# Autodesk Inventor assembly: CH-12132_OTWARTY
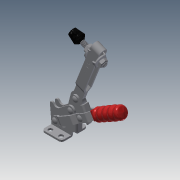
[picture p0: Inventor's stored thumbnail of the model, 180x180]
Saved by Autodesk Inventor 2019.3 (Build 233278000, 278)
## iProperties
Company: Î¢ÈíÖÐ¹ú
Created: 2012-09
Part Number: CH-12132_OTWARTY
Material: Ogólny
Description: STEP AP203
Document SubType Name: Assembly
Designer: CADENGINEERING4
Sending System: SolidWorks 2010
Preprocessor: SwSTEP 2.0
Title: CH-12132.STEP
Author: Î¢ÈíÓÃ»§
Revision Number: ÈÎºÎ
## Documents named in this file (12)
- D:\Vault_2016\Projekty\STRONA\Vertical toggle clamp\Do zrobienia 3\CH-12132\CH-12132_OTWARTY.iam
- D:\Vault_2016\Projekty\STRONA\Vertical toggle clamp\Do zrobienia 3\CH-12132\CH-12130-08.ipt
- D:\Vault_2016\Projekty\STRONA\Vertical toggle clamp\Do zrobienia 3\CH-12132\CH-12130-07.ipt
- D:\Vault_2016\Projekty\STRONA\Vertical toggle clamp\Do zrobienia 3\CH-12132\CH-12130-06.ipt
- D:\Vault_2016\Projekty\STRONA\Vertical toggle clamp\Do zrobienia 3\CH-12132\CH-FW-516.ipt
- D:\Vault_2016\Projekty\STRONA\Vertical toggle clamp\Do zrobienia 3\CH-12132\CH-12130-04 CONNECTING-PLATE.ipt
- D:\Vault_2016\Projekty\STRONA\Vertical toggle clamp\Do zrobienia 3\CH-12132\CH-12130-01 FLANGED BASE.ipt
- D:\Vault_2016\Projekty\STRONA\Vertical toggle clamp\Do zrobienia 3\CH-12132\CH-12130-05.ipt
- D:\Vault_2016\Projekty\STRONA\Vertical toggle clamp\Do zrobienia 3\CH-12132\CH-FC-56212 SPINDLE SUPPLIED.ipt
- D:\Vault_2016\Projekty\STRONA\Vertical toggle clamp\Do zrobienia 3\CH-12132\CH-12130-03 STRAIGHT HANDLE.ipt
- D:\Vault_2016\Projekty\STRONA\Vertical toggle clamp\Do zrobienia 3\CH-12132\CH-FC-56212 Nut.ipt
- D:\Vault_2016\Projekty\STRONA\Vertical toggle clamp\Do zrobienia 3\CH-12132\CH-12132-02 LONG U-BAR.ipt
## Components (15 placed, 11 different names)
1. CH-12130-01 FLANGED BASE_7
2. CH-12130-08:3 — Zestawiające:1, Zestawiające:2, Zestawiające:3, Zestawiające:32
3. CH-12130-07:2 — Zestawiające:16, Zestawiające:17, Zestawiające:18
4. CH-12130-06:3 — Zestawiające:4, Zestawiające:5, Zestawiające:6, Zestawiające:7
5. CH-FW-516:3 — Zestawiające:24, Zestawiające:25, Zestawiające:28
6. CH-12130-08:4 — Zestawiające:10, Zestawiające:11, Zestawiające:12, Zestawiające:13, Zestawiające:14, Zestawiające:15
7. CH-12130-04 CONNECTING-PLATE:2 — Zestawiające:4, Zestawiające:6, Zestawiające:7, Zestawiające:8, Zestawiające:9, Zestawiające:10, Zestawiające:11, Zestawiające:20
8. CH-12130-06:4 — Zestawiające:19, Zestawiające:20
9. CH-12130-05:2 — Zestawiające:1, Równoległe:1
10. CH-FW-516:4 — Zestawiające:23, Zestawiające:26, Zestawiające:27
11. CH-FC-56212 SPINDLE SUPPLIED:2 — Zestawiające:21, Równoległe:2
12. CH-12130-03 STRAIGHT HANDLE:2 — Zestawiające:2, Zestawiające:3, Zestawiające:9, Zestawiające:12, Zestawiające:13, Zestawiające:14, Zestawiające:15, Zestawiające:16, Zestawiające:17, Zestawiające:18, Zestawiające:32
13. CH-FC-56212 Nut:3 — Zestawiające:21, Zestawiające:22, Zestawiające:28
14. CH-FC-56212 Nut:4 — Zestawiające:22, Zestawiające:23, Zestawiające:24, Zestawiające:27, Zestawiające:29, Zestawiające:30
15. CH-12132-02 LONG U-BAR:2 — Równoległe:1, Zestawiające:5, Zestawiające:8, Zestawiające:19, Zestawiające:25, Zestawiające:26, Równoległe:2, Zestawiające:29, Zestawiające:30
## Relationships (33: Mate 31, Flush 2)
- Zestawiające:1 [Mate]: CH-12130-08:3 ↔ CH-12130-05:2
- Zestawiające:2 [Mate]: CH-12130-08:3 ↔ CH-12130-03 STRAIGHT HANDLE:2
- Zestawiające:3 [Mate]: CH-12130-08:3 ↔ CH-12130-03 STRAIGHT HANDLE:2
- Równoległe:1 [Flush]: CH-12130-05:2 ↔ CH-12132-02 LONG U-BAR:2
- Zestawiające:4 [Mate]: CH-12130-06:3 ↔ CH-12130-04 CONNECTING-PLATE:2
- Zestawiające:5 [Mate]: CH-12130-06:3 ↔ CH-12132-02 LONG U-BAR:2
- Zestawiające:6 [Mate]: CH-12130-06:3 ↔ CH-12130-04 CONNECTING-PLATE:2
- Zestawiające:7 [Mate]: CH-12130-06:3 ↔ CH-12130-04 CONNECTING-PLATE:2
- Zestawiające:8 [Mate]: CH-12130-04 CONNECTING-PLATE:2 ↔ CH-12132-02 LONG U-BAR:2
- Zestawiające:9 [Mate]: CH-12130-04 CONNECTING-PLATE:2 ↔ CH-12130-03 STRAIGHT HANDLE:2
- Zestawiające:10 [Mate]: CH-12130-08:4 ↔ CH-12130-04 CONNECTING-PLATE:2
- Zestawiające:11 [Mate]: CH-12130-08:4 ↔ CH-12130-04 CONNECTING-PLATE:2
- Zestawiające:12 [Mate]: CH-12130-08:4 ↔ CH-12130-03 STRAIGHT HANDLE:2
- Zestawiające:13 [Mate]: CH-12130-08:4 ↔ CH-12130-03 STRAIGHT HANDLE:2
- Zestawiające:14 [Mate]: CH-12130-08:4 ↔ CH-12130-03 STRAIGHT HANDLE:2
- Zestawiające:15 [Mate]: CH-12130-08:4 ↔ CH-12130-03 STRAIGHT HANDLE:2
- Zestawiające:16 [Mate]: CH-12130-07:2 ↔ CH-12130-03 STRAIGHT HANDLE:2
- Zestawiające:17 [Mate]: CH-12130-07:2 ↔ CH-12130-03 STRAIGHT HANDLE:2
- Zestawiające:18 [Mate]: CH-12130-07:2 ↔ CH-12130-03 STRAIGHT HANDLE:2
- Zestawiające:19 [Mate]: CH-12130-06:4 ↔ CH-12132-02 LONG U-BAR:2
- Zestawiające:20 [Mate]: CH-12130-04 CONNECTING-PLATE:2 ↔ CH-12130-06:4
- Zestawiające:21 [Mate]: CH-FC-56212 SPINDLE SUPPLIED:2 ↔ CH-FC-56212 Nut:3
- Zestawiające:22 [Mate]: CH-FC-56212 Nut:3 ↔ CH-FC-56212 Nut:4
- Zestawiające:23 [Mate]: CH-FW-516:4 ↔ CH-FC-56212 Nut:4
- Zestawiające:24 [Mate]: CH-FW-516:3 ↔ CH-FC-56212 Nut:4
- Zestawiające:25 [Mate]: CH-FW-516:3 ↔ CH-12132-02 LONG U-BAR:2
- Zestawiające:26 [Mate]: CH-FW-516:4 ↔ CH-12132-02 LONG U-BAR:2
- Zestawiające:27 [Mate]: CH-FW-516:4 ↔ CH-FC-56212 Nut:4
- Zestawiające:28 [Mate]: CH-FW-516:3 ↔ CH-FC-56212 Nut:3
- Równoległe:2 [Flush]: CH-FC-56212 SPINDLE SUPPLIED:2 ↔ CH-12132-02 LONG U-BAR:2
- Zestawiające:29 [Mate]: CH-FC-56212 Nut:4 ↔ CH-12132-02 LONG U-BAR:2
- Zestawiające:30 [Mate]: CH-FC-56212 Nut:4 ↔ CH-12132-02 LONG U-BAR:2
- Zestawiające:32 [Mate]: CH-12130-08:3 ↔ CH-12130-03 STRAIGHT HANDLE:2
